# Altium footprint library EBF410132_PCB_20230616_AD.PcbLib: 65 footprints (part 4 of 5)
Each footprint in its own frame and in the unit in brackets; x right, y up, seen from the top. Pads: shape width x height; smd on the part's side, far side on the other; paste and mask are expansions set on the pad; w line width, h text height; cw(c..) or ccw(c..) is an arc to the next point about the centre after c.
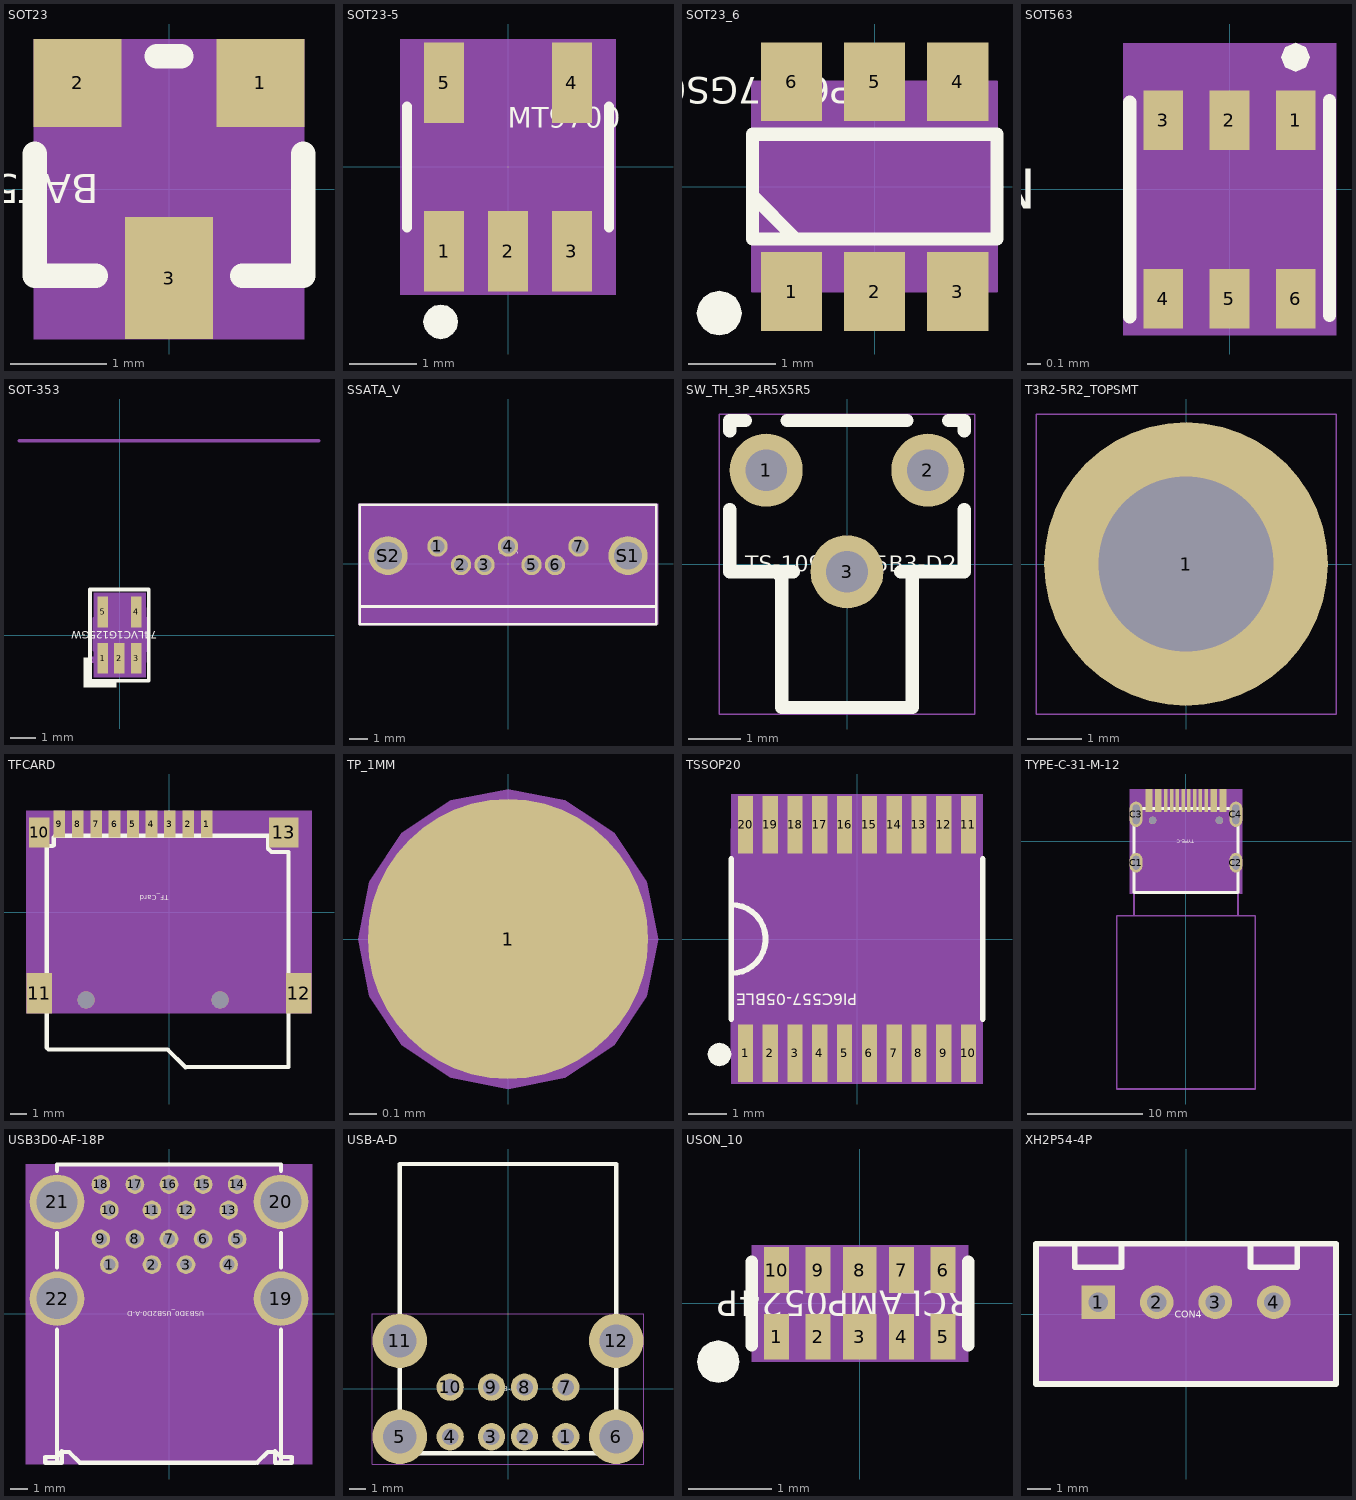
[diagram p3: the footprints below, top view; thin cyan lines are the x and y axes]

## SOT23 [mil] "SOT23"
pads (3):
  rect 36x36 smd: 1(37.5,43.5) 2(-37.5,43.5)
  rect 36x50 smd: 3(0,-36.5)
Top Overlay:
  lines w10: -55,14.5 -55,-35.5 -30,-35.5 ; -5,54.5 5,54.5 ; 30,-35.5 55,-35.5 55,14.5
  text "BAT54C" at -28.8,6 h12
Top 3D Body:
  region: 55.5,61.5 55.5,-61.5 -55.5,-61.5 -55.5,61.5
Mechanical 15:
  text "2" at -55.5,43.5 h45
  text "1" at 19.5,43.5 h45
  text "3" at -18,-36.5 h45
3D body: height 150, standoff 0, extent -55.5,-61.5 55.5,61.5

## SOT23-5 [mm] "SOT23-5"
pads (5):
  rect 0.599x1.199 smd: 1(-0.95,-1.25) 2(0,-1.25) 3(0.95,-1.25) 4(0.95,1.25) 5(-0.95,1.25)
Top Overlay:
  dashed: -1,-2.555 -0.902,-2.535 -0.82,-2.48 -0.765,-2.398 -0.745,-2.3 -0.765,-2.202 -0.783,-2.175 -0.82,-2.12 -0.902,-2.065 -1,-2.045 -1.098,-2.065 -1.18,-2.12 -1.217,-2.175 -1.235,-2.202 -1.255,-2.3 -1.235,-2.398 -1.18,-2.48 -1.098,-2.535
  lines w0.15: -1.5,-0.9 -1.5,0.9 ; 1.5,-0.9 1.5,0.9
  text "MT9700" at 0,0.579 h0.3
Top 3D Body:
  region: -1.6,1.9 -1.6,-1.9 1.6,-1.9 1.6,1.9
Mechanical 15:
  text "5" at -0.95,1.29 h0.1
  text "2" at 0,-1.21 h0.1
  text "1" at -0.95,-1.21 h0.1
  text "3" at 0.95,-1.21 h0.1
  text "4" at 0.95,1.29 h0.1
Top Assembly:
  lines w0.15: -1.5,-0.85 1.5,-0.85 1.5,0.85 -1.5,0.85 -1.5,-0.85
3D body: height 3.81, standoff 0, extent -1.6,-1.9 1.6,1.9

## SOT23_6 [mm] "SOT23_6"
pads (6):
  rect 0.7x0.9 smd: 1(-0.95,-1.2) 2(0,-1.2) 3(0.95,-1.2) 4(0.95,1.2) 5(0,1.2) 6(-0.95,1.2)
Top Overlay:
  dashed: -1.778,-1.703 -1.876,-1.683 -1.958,-1.628 -2.014,-1.545 -2.033,-1.448 -2.014,-1.35 -1.995,-1.323 -1.958,-1.268 -1.876,-1.212 -1.778,-1.193 -1.68,-1.212 -1.598,-1.268 -1.561,-1.323 -1.542,-1.35 -1.523,-1.448 -1.542,-1.545 -1.598,-1.628 -1.68,-1.683
  lines w0.15: -1.4,-0.1 -0.9,-0.6 ; -1.4,-0.6 -1.4,0.6 1.4,0.6 1.4,-0.6 -1.4,-0.6
  text "TP6327GS6" at 0,1.25 h0.3
Top 3D Body:
  region: -1.4,-1.2 -1.4,1.2 1.4,1.2 1.4,-1.2
Mechanical 15:
  text "1" at -0.95,-0.946 h0.64
  text "5" at 0,1.454 h0.64
  text "4" at 0.95,1.454 h0.64
  text "2" at 0,-0.946 h0.64
  text "6" at -0.95,1.454 h0.64
  text "3" at 0.95,-0.946 h0.64
Top Assembly:
  lines w0.025: -1.4,-1.2 -1.4,1.2 1.4,1.2 1.4,-1.2 -1.4,-1.2
3D body: height 3.81, standoff 0, extent -1.4,-1.2 1.4,1.2

## SOT563 [mm] "SOT563"
pads (6):
  rect 0.3x0.45 smd: 1(0.499,0.521) 2(-0.001,0.521) 3(-0.501,0.521) 4(-0.501,-0.829) 5(-0.001,-0.829) 6(0.499,-0.829)
Top Overlay:
  dashed: 0.607,0.996 0.575,0.92 0.499,0.888 0.448,0.909 0.422,0.92 0.391,0.996 0.422,1.073 0.448,1.084 0.499,1.105 0.575,1.073
  lines w0.1: -0.754,-0.966 -0.754,0.657 ; 0.754,-0.955 0.754,0.668
  text "NUP5120X6T1G" at -1.463,0.152 h0.3
Top 3D Body:
  region: 0.804,1.104 0.804,-1.104 -0.804,-1.104 -0.804,1.104
Mechanical 15:
  text "2" at -0.245,0.521 h0.3
  text "4" at -0.745,-0.829 h0.3
  text "6" at 0.255,-0.829 h0.3
  text "5" at -0.245,-0.829 h0.3
  text "1" at 0.255,0.521 h0.3
  text "3" at -0.745,0.521 h0.3
3D body: height 3.81, standoff 0, extent -0.804,-1.104 0.804,1.104

## SOT-353 [mil] "SOT-353"
pads (5):
  rect 16x47 smd: 1(-25.91,-35.43) 2(-0.32,-35.43) 3(25.28,-35.43) 4(25.28,35.43) 5(-25.91,35.43)
Top Overlay:
  dashed: -45.31,-35 -55.31,-35 -55.31,-80 -5.32,-80 -5.32,-70 -45.31,-70
  lines w6: -45.31,-70 44.69,-70 44.69,70 -45.31,70 -45.31,-70
  text "74LVC1G125GW" at 57.6,6 h12
Mechanical 5:
  dashed: -39.69,-65 39.69,-65 39.69,65 -39.69,65
Top 3D Body:
  region: -39.69,-65 39.69,-65 39.69,65 -39.69,65
Top Component Center:
  circle w1: c-0.32,0 r11.81
  circle w1: c-0.32,0 r11.81
  lines w1: -16.06,0 15.43,0 -16.06,0 ; -0.32,-15.75 -0.32,15.75 -0.32,-15.75
Mechanical 15:
  text "5" at -19.11,35.43 h17
  text "1" at -19.11,-35.43 h17
  text "3" at 32.08,-35.43 h17
  text "2" at 6.49,-35.43 h17
  text "4" at 32.08,35.43 h17
Top Assembly:
  circle w3.94: c-41.31,-38 r2.83
  lines w3.94: -32.31,-24 -32.31,-40.83 -20.32,-40.83 ; -31.5,26 -31.5,40.83 ; -31.5,41.83 -19.5,41.83 -19.5,26 ; -20.32,-40 -20.32,-25 ; -6.32,-24 -6.32,-40.83 5.68,-40.83 ; 5.68,-40 5.68,-24 ; 19.68,-24 19.68,-40.83 31.68,-40.83 ; 19.68,26 19.68,41 ; 19.68,41.83 31.68,41.83 31.68,26 ; 31.68,-40 31.68,-24 ; -39.31,-23.61 40.69,-23.61 40.69,25.61 -39.31,25.61 -39.31,-23.61
  text ".Designator" at 42.69,-21 h40
Mechanical 18:
  lines w5: -154.31,298 305.69,298
  text "Remark: ***" at -124.31,98 h25
  text "Rev   : A1" at -124.31,138 h25
  text "Date  : 2007-11-30" at -124.31,178 h25
  text "Creat : Yuki" at -124.31,218 h25
  text "Ref PN: ESDALC6V1W5" at -124.31,258 h25
  text "Sofer Lib Information" at -154.31,308 h25
Mechanical 20:
  lines w1: -39.31,-41 40.69,-41 40.69,42 -39.31,42 -39.31,-41
Mechanical 21:
  text "Approved" at 111.69,0 h35
Mechanical 22:
  text "SOT-353" at 88.69,-163 h30
3D body: height 150, standoff 0, extent -39.69,-65 39.69,65

## SSATA_V [mm] "SSATA_V"
pads (9):
  round 1.1 hole 0.75: 1(-3.81,0.95) 2(-2.54,-0.05) 3(-1.27,-0.05) 4(0,0.95) 5(1.27,-0.05) 6(2.54,-0.05) 7(3.81,0.95)
  round 2.1 hole 1.5: S1(6.48,0.45) S2(-6.48,0.45)
Top Overlay:
  lines w0.15: -8,-2.3 8,-2.3 ; -8,-3.25 8,-3.25 8,3.2 -8,3.2 -8,-3.25
  text "SATA" at -0.488,0.548 h0.3
Top 3D Body:
  region: -8.1,3.25 -8.1,-3.25 8.1,-3.25 8.1,3.25
Mechanical 15:
  text "S1" at 6.3,0.25 h0.64
  text "S2" at -6.8,0.25 h0.64
  text "7" at 3.302,0.95 h0.64
  text "4" at -0.508,0.95 h0.64
  text "1" at -4.318,0.95 h0.64
  text "6" at 2.032,-0.05 h0.64
  text "5" at 0.762,-0.05 h0.64
  text "3" at -1.778,-0.05 h0.64
  text "2" at -3.048,-0.05 h0.64
Top Assembly:
  lines w0.15: -8,3.2 8,3.2 8,-2.3 ; -8,3.2 -8,-2.3 8,-2.3 ; -8,3.2 -8,-3.25 8,-3.25 8,-2.3 ; -8,-1.55 8,-1.55 8,2.45 -8,2.45 -8,-1.55
3D body: height 3.81, standoff 0, extent -8.1,-3.25 8.1,3.25

## SW_TH_3P_4R5X5R5 [mm] "SW_TH_3P_4R5X5R5"
pads (3):
  round 1.4 hole 0.8: 1(-1.55,1.8) 2(1.55,1.8) 3(0,-0.15)
Top Overlay:
  lines w0.254: -2.25,1.044 -2.25,-0.15 -1.031,-0.15 ; -2.25,2.556 -2.25,2.75 -1.947,2.75 ; -1.359,-0.15 -1.25,-0.259 -1.25,-2.75 1.25,-2.75 1.25,-0.15 ; -1.153,2.75 1.153,2.75 ; 1.031,-0.15 2.25,-0.15 2.25,1.044 ; 1.947,2.75 2.25,2.75 2.25,2.556
  text "TS-1091B-A5B3-D2" at -1.951,-0.152 h0.3
Top 3D Body:
  lines w0.025: -2.452,-2.877 2.452,-2.877 2.452,2.877 -2.452,2.877 -2.452,-2.877
Mechanical 15:
  text "2" at 1.296,1.8 h0.64
  text "1" at -1.804,1.8 h0.64
  text "3" at -0.254,-0.15 h0.64

## T3R2-5R2_TOPSMT [mm] "T3R2-5R2_TOPSMT"
pads (1):
  round 5.2 hole 3.2: 1(0,0)
Top Overlay:
  text "M2X3mm" at -1.27,0 h0.3
Top 3D Body:
  lines w0.025: -2.75,-2.75 2.75,-2.75 2.75,2.75 -2.75,2.75 -2.75,-2.75
Mechanical 15:
  text "1" at -0.122,0 h0.3

## TFCARD [mil] "TFCARD"
pads (15):
  rect 27.56x62.99 smd: 1(88.58,206.82) 2(45.27,206.82) 3(1.97,206.82) 4(-41.34,206.82) 5(-84.65,206.82) 6(-127.95,206.82) 7(-171.26,206.82) 8(-214.57,206.82) 9(-257.88,206.82)
  rect 47.24x70 smd: 10(-305.12,187.13)
  rect 60x95 smd: 11(-305.12,-190.81) 12(305.12,-190.81)
  rect 70x70 smd: 13(269.68,187.13)
  round 40 hole 40 unplated: ""(-194.88,-206.56) ""(120.08,-206.56)
Top Overlay:
  lines w10: -289.12,155.19 -287.12,153.19 -287.12,-318.81 -283.12,-322.81 -3.12,-322.81 38.88,-364.81 280.88,-364.05 280.88,141.19 240.88,141.19 232.88,149.19 232.88,179.19 -267.12,179.19 -271.12,175.19 -271.12,157.19 -273.12,155.19 -289.12,155.19
  text "TF_Card" at -0.01,39.6 h12
Top 3D Body:
  region: -335.12,-238.31 -335.12,238.31 335.12,238.31 335.12,-238.31
Mechanical 15:
  text "6" at -127.95,218.82 h30
  text "13" at 269.68,211.13 h30
  text "12" at 305.12,-166.81 h30
  text "11" at -305.12,-166.81 h30
  text "10" at -305.12,211.13 h30
  text "1" at 88.58,218.82 h30
  text "5" at -84.65,218.82 h30
  text "7" at -171.26,218.82 h30
  text "8" at -214.57,218.82 h30
  text "3" at 1.97,218.82 h30
  text "9" at -257.88,218.82 h30
  text "2" at 45.27,218.82 h30
  text "4" at -41.34,218.82 h30
3D body: height 150, standoff 0, extent -335.12,-238.31 335.12,238.31

## TP_1MM [mil] "TP_1MM"
pads (1):
  round 40 smd: 1(0,0)
Top 3D Body:
  region: -21.41,0 -19.78,-8.19 -15.14,-15.14 -8.19,-19.78 0,-21.41 8.19,-19.78 10.52,-18.23 15.14,-15.14 19.78,-8.19 21.41,0 19.78,8.19 15.14,15.14 10.52,18.23 8.19,19.78 0,21.41 -8.19,19.78 -15.14,15.14 -19.78,8.19
Mechanical 15:
  text "1" at 29,-11 h25
Top Assembly:
  dashed: -21.41,0 -19.78,-8.19 -15.14,-15.14 -8.19,-19.78 0,-21.41 8.19,-19.78 10.52,-18.23 15.14,-15.14 19.78,-8.19 21.41,0 19.78,8.19 15.14,15.14 10.52,18.23 8.19,19.78 0,21.41 -8.19,19.78 -15.14,15.14 -19.78,8.19
3D body: height 150, standoff 0, extent -21.41,-21.41 21.41,21.41

## TSSOP20 [mm] "TSSOP20"
pads (20):
  rect 0.4x1.5 smd: 1(-2.925,-3) 2(-2.275,-3) 3(-1.625,-3) 4(-0.975,-3) 5(-0.325,-3) 6(0.325,-3) 7(0.975,-3) 8(1.625,-3) 9(2.275,-3) 10(2.925,-3) 11(2.925,3) 12(2.275,3) 13(1.625,3) 14(0.975,3) 15(0.325,3) 16(-0.325,3) 17(-0.975,3) 18(-1.625,3) 19(-2.275,3) 20(-2.925,3)
Top Overlay:
  dashed: -3.61,-2.724 -3.727,-2.747 -3.826,-2.814 -3.892,-2.913 -3.915,-3.03 -3.892,-3.147 -3.87,-3.18 -3.826,-3.246 -3.727,-3.313 -3.61,-3.336 -3.493,-3.313 -3.393,-3.246 -3.349,-3.18 -3.327,-3.147 -3.304,-3.03 -3.327,-2.913 -3.393,-2.814 -3.493,-2.747
  lines w0.15: -3.3,-2.1 -3.3,2.1 ; -3.3,-0.9 ccw(c-3.3,0) -3.3,0.9 ; 3.3,-2.1 3.3,2.1
  text "PI6C557-05BLE" at 0,-1.433 h0.3
Top 3D Body:
  region: -3.3,-3.8 3.3,-3.8 3.3,3.8 -3.3,3.8
Mechanical 15:
  text "6" at 0.325,-3.203 h0.51
  text "1" at -2.925,-3.203 h0.51
  text "10" at 2.925,-3.406 h0.51
  text "18" at -1.625,2.594 h0.51
  text "8" at 1.625,-3.203 h0.51
  text "19" at -2.275,2.594 h0.51
  text "20" at -2.925,2.594 h0.51
  text "17" at -0.975,2.594 h0.51
  text "2" at -2.275,-3.203 h0.51
  text "7" at 0.975,-3.203 h0.51
  text "3" at -1.625,-3.203 h0.51
  text "9" at 2.275,-3.203 h0.51
  text "16" at -0.325,2.594 h0.51
  text "4" at -0.975,-3.203 h0.51
  text "15" at 0.325,2.594 h0.51
  text "5" at -0.325,-3.203 h0.51
  text "12" at 2.275,2.594 h0.51
  text "11" at 2.925,2.594 h0.51
  text "14" at 0.975,2.594 h0.51
  text "13" at 1.625,2.594 h0.51
Top Assembly:
  lines w0.025: -3.3,-2.9 3.3,-2.9 3.3,2.9 -3.3,2.9 -3.3,-2.9
3D body: height 3.81, standoff 0, extent -3.3,-3.8 3.3,3.8

## TYPE-C-31-M-12 [mm] "TYPE-C-31-M-12"
pads (22):
  rect 0.3x2 smd: A1(-3.35,3.539) A4(-2.55,3.539) A5(-1.25,3.539) A6(-0.249,3.539) A7(0.249,3.539) A8(1.25,3.539) A9(2.55,3.539) A12(3.35,3.539) B1(3.05,3.539) B4(2.25,3.539) B5(1.75,3.539) B6(0.749,3.539) B7(-0.749,3.539) B8(-1.75,3.539) B9(-2.25,3.539) B12(-3.05,3.539)
  oval 1.1x1.7 hole 1.2 slot 0.6 at 0 deg: C1(-4.32,-1.84) C2(4.32,-1.84)
  oval 1.1x2.2 hole 1.7 slot 0.6 at 0 deg: C3(-4.32,2.351) C4(4.32,2.351)
  round 0.65 hole 0.65 unplated: ""(-2.89,1.82) ""(2.89,1.82)
Top Overlay:
  lines w0.249: -4.501,-4.431 4.501,-4.431 4.501,2.861 -4.501,2.861 -4.501,-4.431
  text "TYPE-C" at 0.732,0.152 h0.3
Top 3D Body:
  region: -4.869,-4.54 4.869,-4.54 4.869,4.54 -4.869,4.54
Mechanical 15:
  text "B5" at 2.055,3.539 h0.38
  text "C4" at 4.625,2.351 h0.38
  text "C2" at 4.625,-1.84 h0.38
  text "C3" at -4.016,2.351 h0.38
  text "C1" at -4.016,-1.84 h0.38
  text "A9" at 2.855,3.539 h0.38
  text "B4" at 2.555,3.539 h0.38
  text "B9" at -1.946,3.539 h0.38
  text "A4" at -2.245,3.539 h0.38
  text "A5" at -0.945,3.539 h0.38
  text "A1" at -3.046,3.539 h0.38
  text "B12" at -2.593,3.539 h0.38
  text "B1" at 3.355,3.539 h0.38
  text "A12" at 3.808,3.539 h0.38
  text "B6" at 1.054,3.539 h0.38
  text "A6" at 0.056,3.539 h0.38
  text "A7" at 0.554,3.539 h0.38
  text "B7" at -0.445,3.539 h0.38
  text "B8" at -1.445,3.539 h0.38
  text "A8" at 1.555,3.539 h0.38
Top Assembly:
  lines w0.15: -4.5,-4.44 -4.5,-6.431 ; 0,-6.431 6,-6.431 6,-21.431 -6,-21.431 -6,-6.431 -4.5,-6.431 ; 4.501,-4.431 4.501,-6.431 -4.5,-6.431
3D body: height 3.81, standoff 0, extent -4.869,-4.54 4.869,4.54

## USB3D0-AF-18P [mm] "USB3D0-AF-18P"
pads (22):
  round 1.1 hole 0.7: 1(-3.5,2.9) 2(-1,2.9) 3(1,2.9) 4(3.5,2.9) 5(4,4.4) 6(2,4.4) 7(0,4.4) 8(-2,4.4) 9(-4,4.4) 10(-3.5,6.1) 11(-1,6.1) 12(1,6.1) 13(3.5,6.1) 14(4,7.6) 15(2,7.6) 16(0,7.6) 17(-2,7.6) 18(-4,7.6)
  round 3.2 hole 2.4: 19(6.57,0.9) 20(6.57,6.58) 21(-6.57,6.58) 22(-6.57,0.9)
Top Overlay:
  lines w0.254: -6.57,-8.74 -6.57,-0.931 ; -6.57,2.731 -6.57,4.749 ; -6.57,8.411 -6.57,8.774 6.57,8.774 6.57,8.411 ; -6.283,-8.057 -6.616,-8.39 -7.257,-8.39 -7.257,-8.72 -6.283,-8.72 -6.283,-8.093 -5.86,-8.093 -5.234,-8.72 5.067,-8.72 ; 5.168,-8.72 5.795,-8.093 6.217,-8.093 6.217,-8.72 7.192,-8.72 7.192,-8.39 6.551,-8.39 6.217,-8.057 ; 6.57,-8.74 6.57,-0.931 ; 6.57,2.731 6.57,4.749
  text "USB3D0_USB2D0-A-D" at 2.073,0.152 h0.3
Top 3D Body:
  region: -8.4,8.8 -8.4,-8.8 8.4,-8.8 8.4,8.8
Mechanical 15:
  text "13" at 4.008,6.1 h0.64
  text "16" at 0.508,7.6 h0.64
  text "4" at 3.754,2.9 h0.64
  text "7" at 0.254,4.4 h0.64
  text "10" at -2.992,6.1 h0.64
  text "9" at -3.746,4.4 h0.64
  text "3" at 1.254,2.9 h0.64
  text "11" at -0.492,6.1 h0.64
  text "12" at 1.508,6.1 h0.64
  text "5" at 4.254,4.4 h0.64
  text "8" at -1.746,4.4 h0.64
  text "19" at 7.078,0.9 h0.64
  text "20" at 7.078,6.58 h0.64
  text "21" at -6.062,6.58 h0.64
  text "22" at -6.062,0.9 h0.64
  text "2" at -0.746,2.9 h0.64
  text "6" at 2.254,4.4 h0.64
  text "1" at -3.246,2.9 h0.64
  text "18" at -3.492,7.6 h0.64
  text "17" at -1.492,7.6 h0.64
  text "15" at 2.508,7.6 h0.64
  text "14" at 4.508,7.6 h0.64
3D body: height 3.81, standoff 0, extent -8.4,-8.8 8.4,8.8

## USB-A-D [mm] "USB-A-D"
pads (12):
  round 1.651 hole 1: 1(3.5,-2.9) 2(1,-2.9) 3(-1,-2.9) 4(-3.5,-2.9) 7(3.5,0.1) 8(1,0.1) 9(-1,0.1) 10(-3.5,0.1)
  round 3.3 hole 2: 5(-6.55,-2.9) 6(6.55,-2.9) 11(-6.55,2.9) 12(6.55,2.9)
Top Overlay:
  lines w0.254: -6.55,-3.9 6.55,-3.9 6.55,13.6 -6.55,13.6 -6.55,-3.9
  text "USB-A-D" at -0.853,-0.152 h0.3
Top 3D Body:
  lines w0.025: -8.2,-4.55 8.2,-4.55 8.2,4.55 -8.2,4.55 -8.2,-4.55
Mechanical 15:
  text "1" at 3.124,-2.9 h0.94
  text "7" at 3.124,0.1 h0.94
  text "4" at -3.876,-2.9 h0.94
  text "10" at -4.252,0.1 h0.94
  text "5" at -6.926,-2.9 h0.94
  text "11" at -7.302,2.9 h0.94
  text "12" at 5.798,2.9 h0.94
  text "6" at 6.174,-2.9 h0.94
  text "8" at 0.624,0.1 h0.94
  text "9" at -1.376,0.1 h0.94
  text "2" at 0.624,-2.9 h0.94
  text "3" at -1.376,-2.9 h0.94

## USON_10 [mm] "USON_10"
pads (10):
  rect 0.3x0.55 smd: 1(-1,-0.4) 2(-0.5,-0.4) 4(0.5,-0.4) 5(1,-0.4) 6(1,0.4) 7(0.5,0.4) 9(-0.5,0.4) 10(-1,0.4)
  rect 0.4x0.55 smd: 3(0,-0.4) 8(0,0.4)
Top Overlay:
  dashed: -1.955,-0.7 -1.935,-0.798 -1.88,-0.88 -1.798,-0.935 -1.7,-0.955 -1.602,-0.935 -1.575,-0.917 -1.52,-0.88 -1.465,-0.798 -1.445,-0.7 -1.465,-0.602 -1.52,-0.52 -1.575,-0.483 -1.602,-0.465 -1.7,-0.445 -1.798,-0.465 -1.88,-0.52 -1.935,-0.602
  lines w0.15: -1.3,-0.5 -1.3,0.5 ; 1.3,-0.5 1.3,0.5
  text "RCLAMP0524P" at 1.341,0.152 h0.3
Top 3D Body:
  region: -1.3,-0.7 1.3,-0.7 1.3,0.7 -1.3,0.7
Mechanical 15:
  text "8" at 0.254,0.4 h0.64
  text "3" at 0.254,-0.4 h0.64
  text "1" at -0.746,-0.4 h0.64
  text "10" at -0.492,0.4 h0.64
  text "7" at 0.754,0.4 h0.64
  text "4" at 0.754,-0.4 h0.64
  text "6" at 1.254,0.4 h0.64
  text "5" at 1.254,-0.4 h0.64
  text "2" at -0.246,-0.4 h0.64
  text "9" at -0.246,0.4 h0.64
3D body: height 3.81, standoff 0, extent -1.3,-0.7 1.3,0.7

## XH2P54-4P [mm] "XH2P54-4P"
pads (4):
  rect 1.45x1.45 hole 0.85: 1(-3.81,0.508)
  round 1.45 hole 0.85: 2(-1.27,0.508) 3(1.27,0.508) 4(3.81,0.508)
Top Overlay:
  lines w0.254: -6.51,-3.032 -6.51,3.048 6.51,3.048 6.51,-3.032 -6.51,-3.032 ; -4.826,2.032 -4.826,3.048 -2.794,3.048 -2.794,2.032 -4.826,2.032 ; 2.794,2.032 2.794,3.048 4.826,3.048 4.826,2.032 2.794,2.032
  text "CON4" at -0.488,-0.152 h0.3
Top 3D Body:
  region: -6.477,-3.048 6.477,-3.048 6.477,3.048 -6.477,3.048
Mechanical 15:
  text "4" at 3.556,0.508 h0.64
  text "1" at -4.064,0.508 h0.64
  text "2" at -1.524,0.508 h0.64
  text "3" at 1.016,0.508 h0.64
3D body: height 3.81, standoff 0, extent -6.477,-3.048 6.477,3.048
